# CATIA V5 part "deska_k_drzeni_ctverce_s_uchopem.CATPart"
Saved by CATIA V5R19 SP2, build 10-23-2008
Part number: deska_k_drzeni_ctverce_s_uchopem
Bounding box of the stored display mesh (mm): x 0 to 155, y -80 to 80, z -80 to 80
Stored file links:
  C:\Users\Martiin\Desktop\9.semestr\Projekt-diplomka\3D model\deska_k_drzeni_ctverce_s_uchopem.CATPart
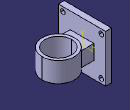
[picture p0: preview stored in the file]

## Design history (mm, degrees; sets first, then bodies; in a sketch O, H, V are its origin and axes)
Body1 (main body)
  Sketch1 on yz-plane, origin (0, 0, 0), H (0, 1, 0), V (0, 0, 1)
    line L1 (-80, 80) -> (80, 80)
    line L2 (80, 80) -> (80, -80)
    line L3 (80, -80) -> (-80, -80)
    line L4 (-80, -80) -> (-80, 80)
    distance L1 H = 80
    distance L3 L1 = 160
    distance L4 V = 80
    distance L4 L2 = 160
    horizontal: L1 H, L3 H
    vertical: L2 V, L4 V
  Pad1: profile Sketch1, direction (1, 0, 0), length 20
  Sketch2 on end face of Pad1, origin (20, 0, 0), H (0, 1, 0), V (0, 0, 1)
  Sketch3 on end face of Pad1, origin (20, 3.9667, 44.8632), H (0, 1, 0), V (0, 0, 1)
    point P1 (-68.9667, 20.1368)
    reference projected line E1 (76.0333, 35.1368) -> (-83.9667, 35.1368) from edge [face of Pad1 from Sketch1.L1 | end face of Pad1]
    reference projected line E2 (-83.9667, 35.1368) -> (-83.9667, -124.8632) from edge [face of Pad1 from Sketch1.L4 | end face of Pad1]
    distance P1 E1 = 15
    distance E2 P1 = 15
  Hole1: placed by Sketch3, at (20, -65, 65) direction (-1, 0, 0), diameter 16, through (limit type 6)
  RectPattern1: of Hole1, direction 1 instances 2, spacing 130, along face of Pad1 from Sketch1.L1
  RectPattern2: of RectPattern1, direction 1 instances 2, spacing 130, along face of Pad1 from Sketch1.L4
  Sketch4 on start face of Pad1, origin (0, 0, 0), H (0, -1, 0), V (0, 0, 1)
    circle A1 centre (0, 0) radius 75
    radius A1 = 75
  Pocket1: profile Sketch4, direction (1, 0, 0), length 5
  Sketch5 on xy-plane, origin (0, 0, 0), H (1, 0, 0), V (0, 1, 0)
    circle A1 centre (100, 0) radius 45
    point P1 (100, 0)
    circle A2 centre (100, 0) radius 55
    radius A1 = 45
    radius A2 = 55
    distance P1 V = 100
    coincidence: P1 H
  Pad2: profile Sketch5, direction (0, 0, 1), length 34, mirrored extent
  Sketch6 on end face of Pad1, origin (20, 0, 0), H (0, 1, 0), V (0, 0, 1)
    line L1 (-40, 25) -> (40, 25)
    line L2 (40, 25) -> (40, -25)
    line L3 (40, -25) -> (-40, -25)
    line L4 (-40, -25) -> (-40, 25)
    distance L1 L3 = 50
    distance H L1 = 25
    distance V L2 = 40
    distance L4 L2 = 80
    horizontal: L1 H, L3 H
    vertical: L2 V, L4 V
  Pad3: profile Sketch6, direction (1, 0, 0), up to the existing solid (limit type 2)
  Mirror1: of the body so far, about xy-plane
  Sketch7 on end face of Pad1, origin (20, 0, 0), H (0, 1, 0), V (0, 0, 1)
    line L1 (-80, 80) -> (80, 80)
    line L2 (80, 80) -> (80, -80)
    line L3 (80, -80) -> (-80, -80)
    line L4 (-80, -80) -> (-80, 80)
    distance L1 H = 80
    distance L3 L1 = 160
    distance L4 V = 80
    distance L4 L2 = 160
    horizontal: L1 H, L3 H
    vertical: L2 V, L4 V
  Pad4: profile Sketch7, direction (1, 0, 0), length 20
Current feature: Mirror1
